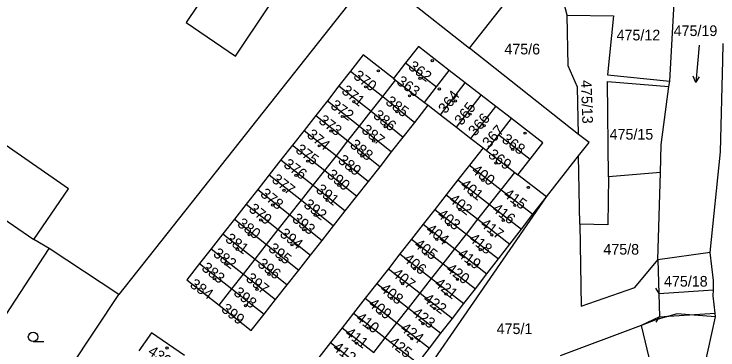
# Model space of a CAD drawing. Extents: x -558358 to -557517, y -1073785 to -1073189.
# Drawn here: x -557909.7 to -557797.5, y -1073343.1 to -1073289.5 of the extents above; entities that cross this region are included whole.
import ezdxf

# ---------------------------------------------------------------- set-up
doc = ezdxf.new("R2010")
doc.units = 0
for name, color, linetype in [('Hranice parcel', 7, 'Continuous'), ('Parcelní čísla', 7, 'Continuous'), ('Vnitřní kresba', 7, 'Continuous'), ('Značky budov', 7, 'Continuous'), ('Značky kultur', 7, 'Continuous')]:
    doc.layers.add(name, color=color, linetype=linetype)

msp = doc.modelspace()

# ---------------------------------------------------------------- linework, layer by layer
at = {"layer": 'Hranice parcel'}
for p, q in [((-557837.1, -1073294.96), (-557823.76, -1073277.98)), ((-557852.38, -1073282.88), (-557892.99, -1073334.25)), ((-557852.38, -1073282.88), (-557837.1, -1073294.96)), ((-557821.55, -1073289.72), (-557823.08, -1073283.72)), ((-557805.19, -1073300.2), (-557804.5, -1073287.75)), ((-557819.71, -1073308.7), (-557837.1, -1073294.96)), ((-557847.28, -1073297.31), (-557849.22, -1073299.81)), ((-557847.28, -1073297.31), (-557842.35, -1073301.13)), ((-557856.07, -1073298.63), (-557857.92, -1073300.99)), ((-557856.07, -1073298.63), (-557850.92, -1073302.67)), ((-557842.35, -1073301.13), (-557840.32, -1073298.51)), ((-557837.79, -1073300.48), (-557840.32, -1073298.51)), ((-557815.1, -1073299.21), (-557805.19, -1073300.2)), ((-557850.92, -1073302.67), (-557848.89, -1073300.07)), ((-557849.22, -1073299.81), (-557848.89, -1073300.07)), ((-557848.89, -1073300.07), (-557844.27, -1073303.61)), ((-557841.74, -1073305.57), (-557837.79, -1073300.48)), ((-557835.23, -1073302.46), (-557837.79, -1073300.48)), ((-557805.35, -1073301.09), (-557805.19, -1073300.2)), ((-557857.92, -1073300.99), (-557859.76, -1073303.34)), ((-557857.92, -1073300.99), (-557852.77, -1073305.03)), ((-557844.27, -1073303.61), (-557842.35, -1073301.13)), ((-557852.77, -1073305.03), (-557850.92, -1073302.67)), ((-557850.92, -1073302.67), (-557845.82, -1073306.79)), ((-557839.19, -1073307.55), (-557835.23, -1073302.46)), ((-557832.93, -1073304.25), (-557835.23, -1073302.46)), ((-557859.76, -1073303.34), (-557861.61, -1073305.7)), ((-557859.76, -1073303.34), (-557854.62, -1073307.38)), ((-557845.82, -1073306.79), (-557843.68, -1073304.07)), ((-557844.27, -1073303.61), (-557843.68, -1073304.07)), ((-557843.68, -1073304.07), (-557841.74, -1073305.57)), ((-557854.62, -1073307.38), (-557852.77, -1073305.03)), ((-557852.77, -1073305.03), (-557847.66, -1073309.15)), ((-557836.88, -1073309.34), (-557832.93, -1073304.25)), ((-557830.43, -1073306.19), (-557832.93, -1073304.25)), ((-557861.61, -1073305.7), (-557863.46, -1073308.06)), ((-557861.61, -1073305.7), (-557856.47, -1073309.74)), ((-557841.74, -1073305.57), (-557839.19, -1073307.55)), ((-557832.44, -1073308.79), (-557830.43, -1073306.19)), ((-557856.47, -1073309.74), (-557854.62, -1073307.38)), ((-557854.62, -1073307.38), (-557849.51, -1073311.5)), ((-557847.66, -1073309.15), (-557845.82, -1073306.79)), ((-557863.46, -1073308.06), (-557865.31, -1073310.42)), ((-557863.46, -1073308.06), (-557858.32, -1073312.1)), ((-557839.19, -1073307.55), (-557836.88, -1073309.34)), ((-557849.51, -1073311.5), (-557847.66, -1073309.15)), ((-557836.88, -1073309.34), (-557834.95, -1073310.84)), ((-557834.38, -1073311.28), (-557832.44, -1073308.79)), ((-557832.44, -1073308.79), (-557827.44, -1073312.66)), ((-557865.31, -1073310.42), (-557867.16, -1073312.77)), ((-557865.31, -1073310.42), (-557860.17, -1073314.46)), ((-557858.32, -1073312.1), (-557856.47, -1073309.74)), ((-557856.47, -1073309.74), (-557851.36, -1073313.85)), ((-557834.95, -1073310.84), (-557837.12, -1073313.61)), ((-557834.95, -1073310.84), (-557834.38, -1073311.28)), ((-557851.36, -1073313.85), (-557849.51, -1073311.5)), ((-557834.38, -1073311.28), (-557829.9, -1073314.76)), ((-557867.16, -1073312.77), (-557869.01, -1073315.13)), ((-557867.16, -1073312.77), (-557862.02, -1073316.82)), ((-557860.17, -1073314.46), (-557858.32, -1073312.1)), ((-557858.32, -1073312.1), (-557853.21, -1073316.21)), ((-557829.38, -1073315.16), (-557827.44, -1073312.66)), ((-557819.52, -1073323.02), (-557819.71, -1073312.13)), ((-557923.1, -1073314.09), (-557906.54, -1073325.46)), ((-557853.21, -1073316.21), (-557851.36, -1073313.85)), ((-557837.12, -1073313.61), (-557838.96, -1073315.96)), ((-557837.12, -1073313.61), (-557832.06, -1073317.52)), ((-557869.01, -1073315.13), (-557870.86, -1073317.49)), ((-557869.01, -1073315.13), (-557863.87, -1073319.18)), ((-557862.02, -1073316.82), (-557860.17, -1073314.46)), ((-557860.17, -1073314.46), (-557855.06, -1073318.56)), ((-557832.06, -1073317.52), (-557829.9, -1073314.76)), ((-557829.9, -1073314.76), (-557829.38, -1073315.16)), ((-557806.64, -1073314.76), (-557814.95, -1073315.46)), ((-557807.11, -1073328.71), (-557806.64, -1073314.76)), ((-557855.06, -1073318.56), (-557853.21, -1073316.21)), ((-557838.96, -1073315.96), (-557840.81, -1073318.32)), ((-557838.96, -1073315.96), (-557833.9, -1073319.88)), ((-557870.86, -1073317.49), (-557872.71, -1073319.85)), ((-557870.86, -1073317.49), (-557865.72, -1073321.53)), ((-557863.87, -1073319.18), (-557862.02, -1073316.82)), ((-557862.02, -1073316.82), (-557856.91, -1073320.91)), ((-557833.9, -1073319.88), (-557832.06, -1073317.52)), ((-557832.06, -1073317.52), (-557826.99, -1073321.44)), ((-557856.91, -1073320.91), (-557855.06, -1073318.56)), ((-557840.81, -1073318.32), (-557842.65, -1073320.68)), ((-557840.81, -1073318.32), (-557835.75, -1073322.24)), ((-557865.72, -1073321.53), (-557863.87, -1073319.18)), ((-557863.87, -1073319.18), (-557858.76, -1073323.27)), ((-557872.71, -1073319.85), (-557874.56, -1073322.2)), ((-557872.71, -1073319.85), (-557867.58, -1073323.89)), ((-557858.76, -1073323.27), (-557856.91, -1073320.91)), ((-557842.65, -1073320.68), (-557844.5, -1073323.04)), ((-557842.65, -1073320.68), (-557837.6, -1073324.6)), ((-557835.75, -1073322.24), (-557833.9, -1073319.88)), ((-557833.9, -1073319.88), (-557828.82, -1073323.81)), ((-557867.58, -1073323.89), (-557865.72, -1073321.53)), ((-557865.72, -1073321.53), (-557860.61, -1073325.62)), ((-557828.82, -1073323.81), (-557826.99, -1073321.44)), ((-557874.56, -1073322.2), (-557876.41, -1073324.56)), ((-557874.56, -1073322.2), (-557869.43, -1073326.25)), ((-557844.5, -1073323.04), (-557846.34, -1073325.39)), ((-557844.5, -1073323.04), (-557839.45, -1073326.96)), ((-557837.6, -1073324.6), (-557835.75, -1073322.24)), ((-557835.75, -1073322.24), (-557830.65, -1073326.18)), ((-557869.43, -1073326.25), (-557867.58, -1073323.89)), ((-557867.58, -1073323.89), (-557862.46, -1073327.97)), ((-557860.61, -1073325.62), (-557858.76, -1073323.27)), ((-557830.65, -1073326.18), (-557828.82, -1073323.81)), ((-557876.41, -1073324.56), (-557878.26, -1073326.92)), ((-557876.41, -1073324.56), (-557871.28, -1073328.61)), ((-557846.34, -1073325.39), (-557848.19, -1073327.75)), ((-557846.34, -1073325.39), (-557841.29, -1073329.31)), ((-557839.45, -1073326.96), (-557837.6, -1073324.6)), ((-557837.6, -1073324.6), (-557832.49, -1073328.56)), ((-557904.1, -1073326.9), (-557906.54, -1073325.46)), ((-557871.28, -1073328.61), (-557869.43, -1073326.25)), ((-557869.43, -1073326.25), (-557864.3, -1073330.32)), ((-557862.46, -1073327.97), (-557860.61, -1073325.62)), ((-557832.49, -1073328.56), (-557830.65, -1073326.18)), ((-557911.75, -1073338.65), (-557904.1, -1073326.9)), ((-557892.99, -1073334.25), (-557904.1, -1073326.9)), ((-557878.26, -1073326.92), (-557880.11, -1073329.28)), ((-557878.26, -1073326.92), (-557873.13, -1073330.97)), ((-557841.29, -1073329.31), (-557839.45, -1073326.96)), ((-557839.45, -1073326.96), (-557834.32, -1073330.93)), ((-557798.75, -1073327.52), (-557807.11, -1073328.71)), ((-557873.13, -1073330.97), (-557871.28, -1073328.61)), ((-557871.28, -1073328.61), (-557866.15, -1073332.68)), ((-557864.3, -1073330.32), (-557862.46, -1073327.97)), ((-557848.19, -1073327.75), (-557850.03, -1073330.11)), ((-557848.19, -1073327.75), (-557843.14, -1073331.67)), ((-557834.32, -1073330.93), (-557832.49, -1073328.56)), ((-557807.11, -1073328.71), (-557806.93, -1073334.05)), ((-557880.11, -1073329.28), (-557874.98, -1073333.33)), ((-557843.14, -1073331.67), (-557841.29, -1073329.31)), ((-557841.29, -1073329.31), (-557836.16, -1073333.3)), ((-557874.98, -1073333.33), (-557873.13, -1073330.97)), ((-557873.13, -1073330.97), (-557868, -1073335.03)), ((-557866.15, -1073332.68), (-557864.3, -1073330.32)), ((-557850.03, -1073330.11), (-557851.88, -1073332.47)), ((-557850.03, -1073330.11), (-557844.98, -1073334.03)), ((-557836.16, -1073333.3), (-557834.32, -1073330.93)), ((-557844.98, -1073334.03), (-557843.14, -1073331.67)), ((-557843.14, -1073331.67), (-557837.99, -1073335.67)), ((-557868, -1073335.03), (-557866.15, -1073332.68)), ((-557851.88, -1073332.47), (-557853.72, -1073334.82)), ((-557851.88, -1073332.47), (-557846.83, -1073336.4)), ((-557911.2, -1073361.51), (-557892.99, -1073334.25)), ((-557877.01, -1073335.92), (-557874.98, -1073333.33)), ((-557874.98, -1073333.33), (-557869.85, -1073337.38)), ((-557846.83, -1073336.4), (-557844.98, -1073334.03)), ((-557844.98, -1073334.03), (-557839.83, -1073338.04)), ((-557837.99, -1073335.67), (-557836.16, -1073333.3)), ((-557806.93, -1073334.05), (-557806.8, -1073337.79)), ((-557869.85, -1073337.38), (-557868, -1073335.03)), ((-557853.72, -1073334.82), (-557855.57, -1073337.18)), ((-557853.72, -1073334.82), (-557848.67, -1073338.75)), ((-557848.67, -1073338.75), (-557846.83, -1073336.4)), ((-557846.83, -1073336.4), (-557841.66, -1073340.41)), ((-557839.83, -1073338.04), (-557837.99, -1073335.67)), ((-557855.57, -1073337.18), (-557857.41, -1073339.54)), ((-557855.57, -1073337.18), (-557850.52, -1073341.11)), ((-557809.37, -1073390.13), (-557797.89, -1073337.76)), ((-557850.52, -1073341.11), (-557848.67, -1073338.75)), ((-557848.67, -1073338.75), (-557843.49, -1073342.78)), ((-557841.66, -1073340.41), (-557839.83, -1073338.04)), ((-557806.8, -1073337.79), (-557809.74, -1073339.14)), ((-557857.41, -1073339.54), (-557859.26, -1073341.9)), ((-557857.41, -1073339.54), (-557852.37, -1073343.47)), ((-557809.74, -1073339.14), (-557822.65, -1073343.99)), ((-557852.37, -1073343.47), (-557850.52, -1073341.11)), ((-557850.52, -1073341.11), (-557845.33, -1073345.15)), ((-557843.49, -1073342.78), (-557841.66, -1073340.41)), ((-557859.26, -1073341.9), (-557861.1, -1073344.25)), ((-557859.26, -1073341.9), (-557854.22, -1073345.83)), ((-557845.33, -1073345.15), (-557843.49, -1073342.78))]:
    msp.add_line(p, q, dxfattribs=at)
for points in [[(-557863.55, -1073279.98), (-557871.4, -1073274.72), (-557882.24, -1073290.87), (-557874.41, -1073296.22), (-557863.55, -1073279.98)], [(-557819.71, -1073308.7), (-557819.88, -1073301.16), (-557821.38, -1073297.78), (-557821.55, -1073289.72)], [(-557821.55, -1073289.72), (-557814.17, -1073289.81), (-557815.1, -1073299.21)], [(-557840.32, -1073298.51), (-557845.25, -1073294.69), (-557847.28, -1073297.31)], [(-557798.75, -1073327.52), (-557797.09, -1073311.5), (-557796.72, -1073296.93), (-557796.66, -1073294.23)], [(-557849.22, -1073299.81), (-557854.03, -1073296.04), (-557856.07, -1073298.63)], [(-557814.95, -1073315.46), (-557815.09, -1073300.29), (-557805.35, -1073301.09)], [(-557806.64, -1073314.76), (-557806.53, -1073310.37), (-557805.35, -1073301.09)], [(-557906.54, -1073325.46), (-557900.99, -1073317.38), (-557917.44, -1073306)], [(-557827.44, -1073312.66), (-557825.43, -1073310.07), (-557830.43, -1073306.19)], [(-557819.71, -1073312.13), (-557818.05, -1073310.01), (-557819.71, -1073308.7)], [(-557856.89, -1073365.11), (-557824.85, -1073318.68), (-557819.71, -1073312.13)], [(-557826.99, -1073321.44), (-557824.85, -1073318.68), (-557829.38, -1073315.16)], [(-557814.95, -1073315.46), (-557815.04, -1073323.14), (-557819.52, -1073323.02)], [(-557819.52, -1073323.02), (-557819.31, -1073336.08), (-557810.73, -1073333.1), (-557807.11, -1073328.71)], [(-557797.89, -1073337.76), (-557797.95, -1073337.19), (-557798.25, -1073334.44), (-557798.23, -1073333.47), (-557798.2, -1073331.98), (-557798.75, -1073327.52)], [(-557880.11, -1073329.28), (-557882.14, -1073331.87), (-557877.01, -1073335.92)], [(-557877.01, -1073335.92), (-557871.88, -1073339.97), (-557869.85, -1073337.38)], [(-557797.89, -1073337.76), (-557802.06, -1073337.47), (-557804.02, -1073337.33), (-557805.31, -1073337.69), (-557807.41, -1073338.27), (-557809.74, -1073339.14)], [(-557809.74, -1073339.14), (-557808.21, -1073345.61), (-557807.79, -1073349.5), (-557808.41, -1073352.55)], [(-557882.54, -1073343.92), (-557887.8, -1073340.34), (-557889.79, -1073343.18)]]:
    msp.add_lwpolyline(points, dxfattribs=at)
at = {"layer": 'Vnitřní kresba'}
for p, q in [((-557807.47, -1073333.21), (-557806.93, -1073334.05)), ((-557806.93, -1073334.05), (-557798.23, -1073333.47)), ((-557806.8, -1073337.79), (-557805.31, -1073337.69)), ((-557805.31, -1073337.69), (-557802.06, -1073337.47)), ((-557802.06, -1073337.47), (-557797.95, -1073337.19)), ((-557807.34, -1073338.63), (-557806.8, -1073337.79))]:
    msp.add_line(p, q, dxfattribs=at)
at = {"layer": 'Značky budov'}
for centre in [(-557843.03, -1073296.97), (-557851.63, -1073298.58), (-557844.99, -1073299.77), (-557853.67, -1073301.13), (-557841.9, -1073301.47), (-557846.66, -1073302.56), (-557855.54, -1073303.48), (-557839.36, -1073303.38), (-557848.65, -1073305.08), (-557857.37, -1073305.86), (-557837.01, -1073305.48), (-557850.54, -1073307.47), (-557834.77, -1073307.3), (-557859.21, -1073308.18), (-557828.24, -1073308.51), (-557852.37, -1073309.77), (-557861.07, -1073310.53), (-557854.22, -1073312.14), (-557830.21, -1073311.11), (-557862.91, -1073312.98), (-557832.87, -1073313.25), (-557864.77, -1073315.23), (-557856.08, -1073314.44), (-557834.96, -1073316.02), (-557866.67, -1073317.61), (-557857.91, -1073316.83), (-557827.72, -1073317.16), (-557836.78, -1073318.36), (-557868.48, -1073319.96), (-557859.79, -1073319.2), (-557838.61, -1073320.72), (-557829.88, -1073320.03), (-557861.68, -1073321.59), (-557870.37, -1073322.34), (-557840.43, -1073323.11), (-557831.72, -1073322.42), (-557863.53, -1073323.92), (-557872.21, -1073324.69), (-557842.3, -1073325.44), (-557833.54, -1073324.73), (-557865.39, -1073326.31), (-557874.11, -1073327.04), (-557844.09, -1073327.8), (-557835.38, -1073327.07), (-557867.24, -1073328.67), (-557875.91, -1073329.36), (-557837.17, -1073329.41), (-557869.07, -1073331.01), (-557845.87, -1073330.1), (-557877.77, -1073331.73), (-557839.01, -1073331.8), (-557870.96, -1073333.4), (-557847.74, -1073332.5), (-557840.85, -1073334.14), (-557849.54, -1073334.84), (-557872.8, -1073335.99), (-557842.67, -1073336.45), (-557851.37, -1073337.26), (-557844.51, -1073338.87), (-557853.19, -1073339.56), (-557846.3, -1073341.26), (-557855.07, -1073341.99), (-557885.3, -1073342.76)]:
    msp.add_circle(centre, 0.175, dxfattribs=at)
at = {"layer": 'Značky kultur'}
for p, q in [((-557800.52, -1073294.48), (-557801.04, -1073300.46)), ((-557801.04, -1073300.46), (-557801.46, -1073299.44)), ((-557801.04, -1073300.46), (-557800.46, -1073299.52)), ((-557906.67, -1073341.73), (-557904.92, -1073341.73))]:
    msp.add_line(p, q, dxfattribs=at)
msp.add_circle((-557906.67, -1073340.98), 0.75, dxfattribs=at)

# ---------------------------------------------------------------- texts
at = {"layer": 'Parcelní čísla'}
for s, p in [('475/19', (-557804.56, -1073293.03)), ('475/12', (-557813.66, -1073293.73)), ('475/6', (-557831.54, -1073295.96)), ('475/15', (-557814.77, -1073309.54)), ('475/8', (-557815.76, -1073327.87)), ('475/18', (-557806.1, -1073332.97)), ('475/1', (-557832.77, -1073340.53))]:
    msp.add_text(s, height=1.7, dxfattribs=at).set_placement(p)
for s, rotation, p in [('362', 324, (-557846.99, -1073298.19)), ('370', 323, (-557855.74, -1073299.67)), ('363', 324, (-557848.85, -1073300.58)), ('475/13', 272, (-557819.35, -1073300.08)), ('371', 322, (-557857.63, -1073302.02)), ('364', 52, (-557840.91, -1073305.51)), ('385', 323, (-557850.62, -1073303.77)), ('372', 324, (-557859.39, -1073304.4)), ('365', 52, (-557838.34, -1073307.39)), ('386', 321, (-557852.58, -1073305.92)), ('373', 323, (-557861.28, -1073306.77)), ('366', 49, (-557836.2, -1073309.09)), ('387', 322, (-557854.45, -1073308.27)), ('367', 48, (-557833.98, -1073310.98)), ('374', 321, (-557863.14, -1073309)), ('388', 321, (-557856.28, -1073310.62)), ('368', 324, (-557832.08, -1073309.81)), ('375', 323, (-557864.97, -1073311.43)), ('369', 324, (-557834.27, -1073312.24)), ('376', 324, (-557866.87, -1073313.78)), ('389', 322, (-557858.19, -1073313.09)), ('400', 323, (-557836.9, -1073314.71)), ('377', 322, (-557868.75, -1073316.16)), ('390', 321, (-557859.96, -1073315.4)), ('401', 321, (-557838.71, -1073316.96)), ('378', 321, (-557870.57, -1073318.43)), ('391', 321, (-557861.71, -1073317.76)), ('402', 322, (-557840.49, -1073319.35)), ('415', 324, (-557831.82, -1073318.54)), ('379', 321, (-557872.42, -1073320.84)), ('392', 322, (-557863.67, -1073320.16)), ('403', 322, (-557842.36, -1073321.74)), ('416', 323, (-557833.63, -1073320.86)), ('393', 321, (-557865.5, -1073322.42)), ('380', 323, (-557874.24, -1073323.22)), ('417', 323, (-557835.5, -1073323.27)), ('394', 322, (-557867.47, -1073324.82)), ('404', 322, (-557844.18, -1073324.12)), ('381', 324, (-557876.15, -1073325.67)), ('418', 322, (-557837.31, -1073325.59)), ('395', 321, (-557869.29, -1073327.14)), ('405', 323, (-557846.05, -1073326.52)), ('382', 323, (-557878.09, -1073327.99)), ('419', 324, (-557839.13, -1073328.09)), ('396', 323, (-557871.01, -1073329.63)), ('406', 321, (-557847.76, -1073328.8)), ('383', 322, (-557879.92, -1073330.25)), ('420', 324, (-557840.95, -1073330.45)), ('397', 321, (-557872.88, -1073331.91)), ('407', 321, (-557849.55, -1073331.16)), ('384', 325, (-557881.8, -1073332.94)), ('421', 322, (-557842.8, -1073332.73)), ('398', 321, (-557874.83, -1073334.16)), ('408', 322, (-557851.48, -1073333.59)), ('422', 324, (-557844.61, -1073335.23)), ('409', 322, (-557853.33, -1073335.97)), ('399', 322, (-557876.79, -1073336.81)), ('423', 323, (-557846.4, -1073337.46)), ('410', 323, (-557855.33, -1073338.24)), ('411', 323, (-557857.07, -1073340.65)), ('424', 323, (-557848.24, -1073339.88)), ('412', 323, (-557859.02, -1073342.96)), ('425', 322, (-557850.11, -1073342.12)), ('430', 327, (-557888.49, -1073343.66))]:
    msp.add_text(s, height=1.7, rotation=rotation, dxfattribs=at).set_placement(p)

doc.saveas('drawing.dxf')
